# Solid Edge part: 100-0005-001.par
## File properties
Title: 100-0005-00.par
Author: rtconerl
Template: ANSIMM.PAR
Last saved by: jccrumbl
Revision: 46
Application: Solid Edge
Revision: A
Teamcenter Item Type: Item
Accuracy: 0.99
TC Engineering Description: Valve Top Plate
TC_ImportTime: 2008-07-08
PartType: -
Last Saved Version: -
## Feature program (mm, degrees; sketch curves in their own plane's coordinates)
pattern "unnamed Pattern 1"
pattern "unnamed Pattern 2"
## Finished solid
Body 1: solid body, 35 faces, 94 edges, 56 vertices.
  Faces by surface: plane 18, cylinder 17
  Edges by curve: line 60, circle 26, ellipse 8
Bounding box of the edges (mm): 60.000 x 60.000 x 10.000, from (-30, -30, 0) to (30, 30, 10).
Cylindrical faces by radius (mm): R2 x4, R5 x4, R7.5 x1, R9.5 x4, R10 x4
Planar faces by outward normal: +x 1, +y 1, +z 5, -x 1, -y 1, -z 1, oblique 8
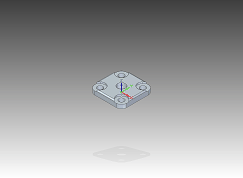
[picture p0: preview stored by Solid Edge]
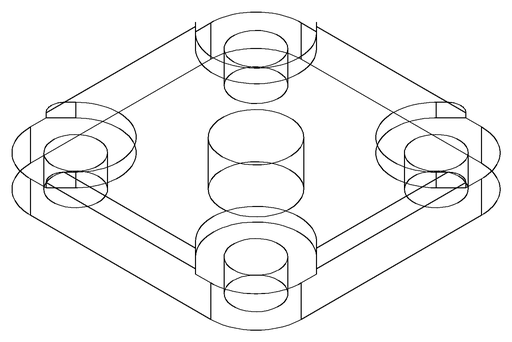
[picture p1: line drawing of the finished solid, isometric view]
